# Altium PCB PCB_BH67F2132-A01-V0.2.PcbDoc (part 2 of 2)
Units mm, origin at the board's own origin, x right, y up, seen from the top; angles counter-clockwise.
Board outline 91.52 x 58.18 mm, 2 copper layers (Top Layer, Bottom Layer); 21 components, 47 nets, 172 pads, 84 vias.
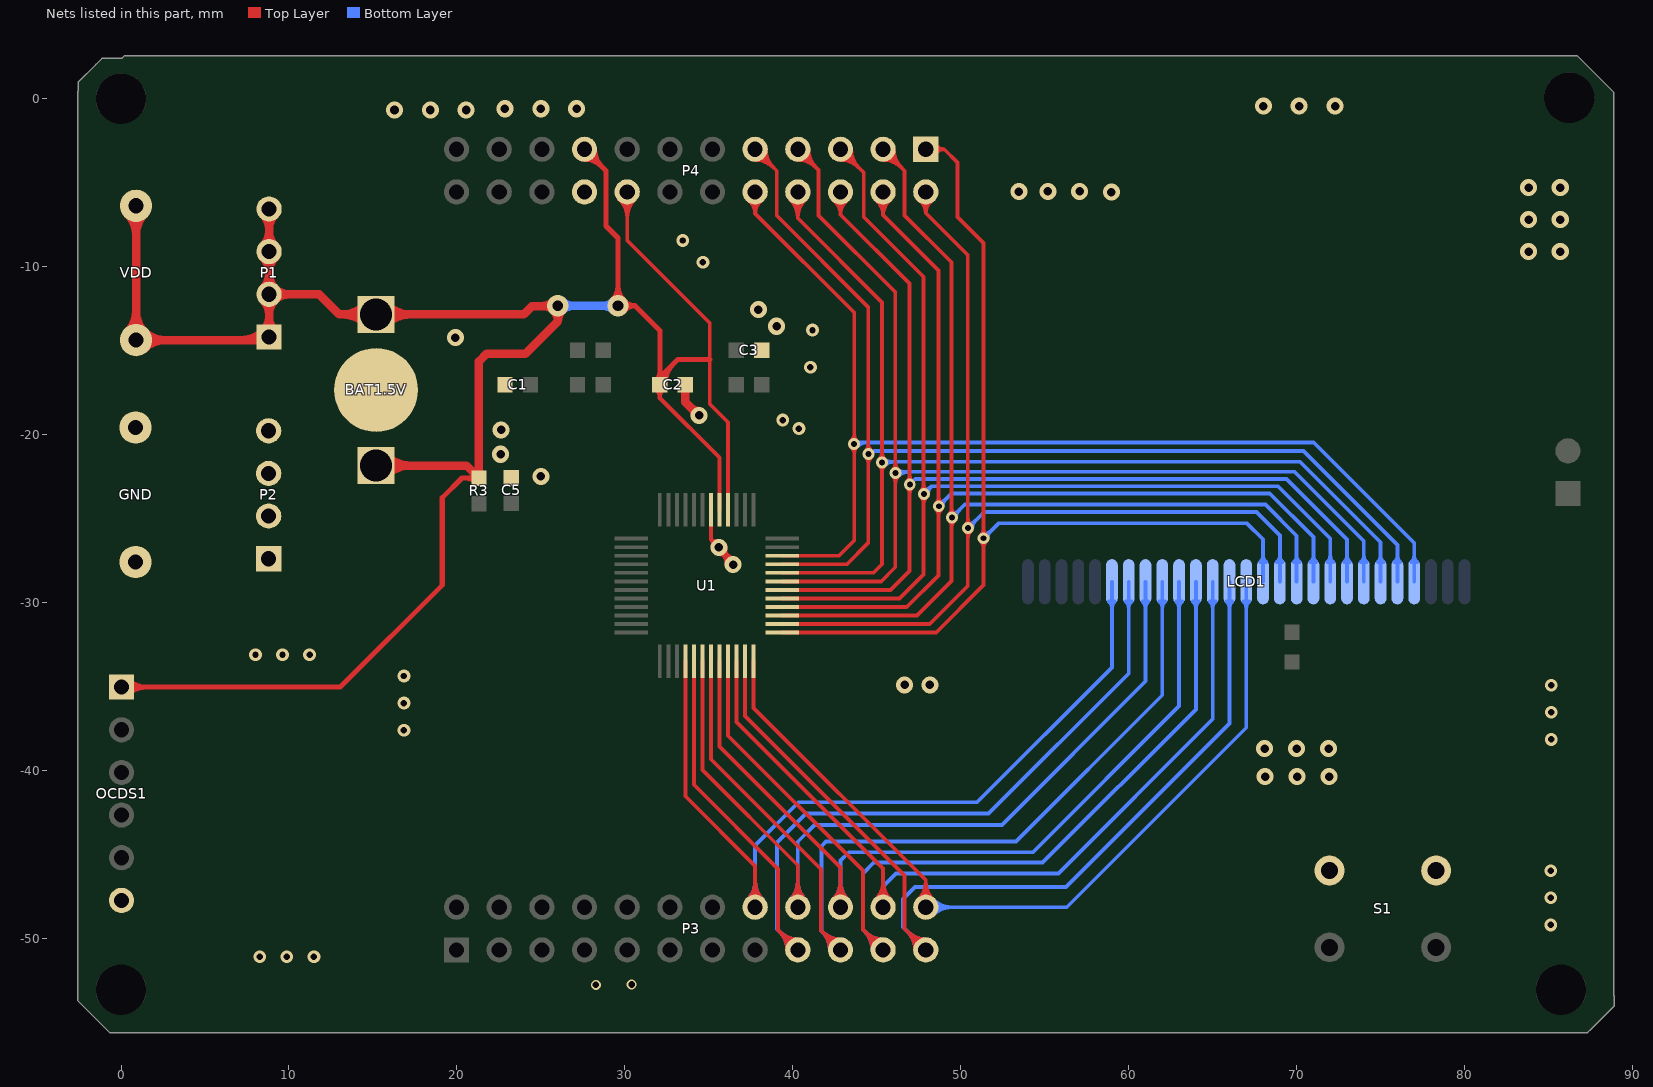
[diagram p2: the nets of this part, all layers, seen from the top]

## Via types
v1: diameter 1.016, hole 0.508, Top Layer to Bottom Layer, tented both sides, 38 vias
v2: diameter 0.762, hole 0.381, Top Layer to Bottom Layer, tented both sides, 23 vias
v3: diameter 0.711, hole 0.356, Top Layer to Bottom Layer, tented both sides, 17 vias
v4: diameter 0.6, hole 0.4, Top Layer to Bottom Layer, tented both sides, 4 vias
v5: diameter 1.27, hole 0.635, Top Layer to Bottom Layer, tented both sides, 2 vias

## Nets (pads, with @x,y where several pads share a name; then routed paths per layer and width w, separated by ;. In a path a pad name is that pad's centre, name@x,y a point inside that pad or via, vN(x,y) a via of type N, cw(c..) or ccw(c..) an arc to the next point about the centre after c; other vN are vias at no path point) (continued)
SEG2: LCD1.4 P4.10 U1.34 | length 72.6
  Top Layer w0.229: P4.10@37.378,-6.056 cw(c36.785,-6.833) 37.763,-6.833 cw(c38.741,-6.833) P4.10@38.148,-6.056 ; P4.10@37.516,-5.874 cw(c37.137,-6.372) 37.763,-6.372 cw(c38.389,-6.372) P4.10@38.01,-5.874 ; P4.10@37.763,-5.55 37.763,-6.833 43.668,-12.738 43.668,-26.302 42.753,-27.216 U1.34@39.385,-27.216 ; v3@43.472,-20.732 cw(c42.999,-21.205) 43.668,-21.205 ; v3@43.472,-20.391 ccw(c42.999,-19.917) 43.668,-19.917 ; 43.668,-21.082 cw(c44.164,-21.082) v3@43.813,-20.732 ; 43.668,-20.04 ccw(c44.164,-20.04) v3@43.813,-20.391
  Bottom Layer w0.229: v3(43.642,-20.561) 43.731,-20.472 71.024,-20.472 77.007,-26.456 LCD1.4@77.007,-28.765 ; v3@43.813,-20.732 cw(c44.44,-21.358) 44.44,-20.472 ; v3@43.813,-20.391 ccw(c44.01,-20.193) 44.01,-20.472 ; LCD1.4@76.841,-27.599 ccw(c76.438,-27.196) 77.007,-27.196 ccw(c77.576,-27.196) LCD1.4@77.174,-27.599
SEG3: LCD1.5 P4.9 U1.33 | length 74.6
  Top Layer w0.229: P4.9@37.763,-3.645 cw(c37.763,-5.18) 38.848,-4.095 cw(c39.933,-3.01) P4.9@38.399,-3.01 ; P4.9@37.763,-3.417 cw(c37.763,-4.4) 38.458,-3.705 cw(c39.153,-3.01) P4.9@38.17,-3.01 ; P4.9@37.763,-3.01 39.045,-4.292 39.045,-6.947 44.493,-12.395 44.493,-26.467 43.236,-27.724 U1.33@39.385,-27.724 ; v3@44.348,-21.316 cw(c43.997,-21.667) 44.493,-21.667 ; v3@44.348,-20.975 ccw(c43.997,-20.624) 44.493,-20.624 ; 44.493,-21.789 cw(c45.163,-21.789) v3@44.689,-21.316 ; 44.493,-20.502 ccw(c45.163,-20.502) v3@44.689,-20.975
  Bottom Layer w0.229: v3(44.519,-21.145) 44.684,-20.98 70.414,-20.98 76.007,-26.574 LCD1.5@76.007,-28.765 ; LCD1.5@75.841,-27.599 ccw(c75.438,-27.196) 76.007,-27.196 ccw(c76.576,-27.196) LCD1.5@76.174,-27.599
SEG4: LCD1.6 P4.8 U1.32 | length 72
  Top Layer w0.229: U1.32@39.385,-28.232 44.811,-28.232 45.319,-27.724 v3(45.319,-21.653) 45.319,-12.128 40.303,-7.113 P4.8@40.303,-5.55 ; P4.8@39.853,-5.999 cw(c38.768,-7.085) 40.303,-7.085 cw(c41.838,-7.085) P4.8@40.753,-5.999 ; P4.8@40.015,-5.838 cw(c39.32,-6.533) 40.303,-6.533 cw(c41.286,-6.533) P4.8@40.591,-5.838 ; v3@45.148,-21.824 cw(c44.736,-22.236) 45.319,-22.236 cw(c45.901,-22.236) v3@45.489,-21.824 ; v3@45.148,-21.483 ccw(c44.736,-21.071) 45.319,-21.071 ccw(c45.901,-21.071) v3@45.489,-21.483
  Bottom Layer w0.229: v3(45.319,-21.653) 45.357,-21.615 70.211,-21.615 75.007,-26.412 LCD1.6@75.007,-28.765 ; v3@45.489,-21.824 cw(c45.993,-22.328) 45.993,-21.615 ; v3@45.489,-21.483 ccw(c45.809,-21.163) 45.809,-21.615 ; LCD1.6@74.841,-27.599 ccw(c74.438,-27.196) 75.007,-27.196 ccw(c75.576,-27.196) LCD1.6@75.174,-27.599
SEG5: LCD1.7 P4.7 U1.31 | length 74
  Top Layer w0.229: U1.31@39.385,-28.74 45.268,-28.74 46.106,-27.902 46.106,-11.519 41.534,-6.947 41.534,-4.241 P4.7@40.303,-3.01 ; P4.7@40.303,-3.645 cw(c40.303,-5.18) 41.388,-4.095 cw(c42.473,-3.01) P4.7@40.939,-3.01 ; P4.7@40.303,-3.417 cw(c40.303,-4.4) 40.998,-3.705 cw(c41.693,-3.01) P4.7@40.71,-3.01 ; v3@45.961,-22.459 cw(c45.61,-22.81) 46.106,-22.81 ; v3@45.961,-22.118 ccw(c45.61,-21.767) 46.106,-21.767 ; 46.106,-22.932 cw(c46.775,-22.932) v3@46.302,-22.459 ; 46.106,-21.645 ccw(c46.775,-21.645) v3@46.302,-22.118
  Bottom Layer w0.229: v3(46.132,-22.288) 46.208,-22.212 69.881,-22.212 74.007,-26.339 LCD1.7@74.007,-28.765 ; v3@46.302,-22.459 cw(c46.898,-23.055) 46.898,-22.212 ; v3@46.302,-22.118 ccw(c46.53,-21.89) 46.53,-22.212 ; LCD1.7@73.841,-27.599 ccw(c73.438,-27.196) 74.007,-27.196 ccw(c74.576,-27.196) LCD1.7@74.174,-27.599
SEG6: LCD1.8 P4.6 U1.30 | length 68.5
  Top Layer w0.229: U1.30@39.385,-29.248 45.827,-29.248 46.944,-28.13 46.944,-11.011 42.843,-6.909 ; P4.6@42.435,-6.038 cw(c41.707,-6.909) 42.843,-6.909 ; P4.6@42.582,-5.862 cw(c42.116,-6.42) 42.843,-6.42 cw(c43.57,-6.42) P4.6@43.104,-5.862 ; P4.6@42.843,-5.55 42.843,-6.909 ; P4.6@43.251,-6.038 ccw(c43.979,-6.909) 42.843,-6.909 ; v3@46.799,-23.145 cw(c46.449,-23.495) 46.944,-23.495 ; v3@46.799,-22.804 ccw(c46.449,-22.453) 46.944,-22.453 ; 46.944,-23.618 cw(c47.614,-23.618) v3@47.14,-23.145 ; 46.944,-22.33 ccw(c47.614,-22.33) v3@47.14,-22.804
  Bottom Layer w0.229: v3(46.97,-22.974) 47.3,-22.644 69.398,-22.644 73.007,-26.253 LCD1.8@73.007,-28.765 ; LCD1.8@72.841,-27.599 ccw(c72.438,-27.196) 73.007,-27.196 ccw(c73.576,-27.196) LCD1.8@73.174,-27.599
SEG7: LCD1.9 P4.5 U1.29 | length 72.2
  Top Layer w0.229: U1.29@39.385,-29.756 46.36,-29.756 47.783,-28.334 47.783,-10.604 44.227,-7.048 44.227,-4.393 P4.5@42.843,-3.01 ; P4.5@42.843,-3.645 cw(c42.843,-5.18) 43.928,-4.095 cw(c45.013,-3.01) P4.5@43.479,-3.01 ; P4.5@42.843,-3.417 cw(c42.843,-4.4) 43.538,-3.705 cw(c44.233,-3.01) P4.5@43.25,-3.01 ; v3@47.637,-23.704 cw(c47.287,-24.054) 47.783,-24.054 ; v3@47.637,-23.362 ccw(c47.287,-23.012) 47.783,-23.012 ; 47.783,-24.177 cw(c48.452,-24.177) v3@47.979,-23.704 ; 47.783,-22.889 ccw(c48.452,-22.889) v3@47.979,-23.362
  Bottom Layer w0.229: v3(47.808,-23.533) 48.265,-23.076 68.89,-23.076 72.007,-26.193 LCD1.9@72.007,-28.765 ; v3@47.808,-23.292 ccw(c47.808,-22.709) 48.22,-23.121 ccw(c48.632,-23.533) v3@48.049,-23.533 ; LCD1.9@71.841,-27.599 ccw(c71.438,-27.196) 72.007,-27.196 ccw(c72.576,-27.196) LCD1.9@72.174,-27.599
SEG8: LCD1.10 P4.4 U1.28 | length 67.6
  Top Layer w0.229: U1.28@39.385,-30.264 46.792,-30.264 48.672,-28.384 48.672,-10.223 45.383,-6.935 ; P4.4@44.969,-6.032 cw(c44.192,-6.935) 45.383,-6.935 ; P4.4@45.118,-5.858 cw(c44.62,-6.437) 45.383,-6.437 cw(c46.146,-6.437) P4.4@45.648,-5.858 ; P4.4@45.383,-5.55 45.383,-6.935 ; P4.4@45.797,-6.032 ccw(c46.574,-6.935) 45.383,-6.935 ; v3@48.526,-24.44 cw(c48.176,-24.791) 48.672,-24.791 ; v3@48.526,-24.099 ccw(c48.176,-23.748) 48.672,-23.748 ; 48.672,-24.913 cw(c49.341,-24.913) v3@48.868,-24.44 ; 48.672,-23.626 ccw(c49.341,-23.626) v3@48.868,-24.099
  Bottom Layer w0.229: v3(48.697,-24.27) 49.459,-23.508 68.407,-23.508 71.007,-26.108 LCD1.10@71.007,-28.765 ; v3@48.697,-24.028 ccw(c48.697,-23.446) 49.109,-23.858 ccw(c49.521,-24.27) v3@48.938,-24.27 ; LCD1.10@70.841,-27.599 ccw(c70.438,-27.196) 71.007,-27.196 ccw(c71.576,-27.196) LCD1.10@71.174,-27.599
SEG9: LCD1.11 P4.3 U1.27 | length 70.3
  Top Layer w0.229: U1.27@39.385,-30.772 47.402,-30.772 49.459,-28.715 49.459,-9.741 46.665,-6.947 46.665,-4.292 P4.3@45.383,-3.01 ; P4.3@45.383,-3.645 cw(c45.383,-5.18) 46.468,-4.095 cw(c47.553,-3.01) P4.3@46.019,-3.01 ; P4.3@45.383,-3.417 cw(c45.383,-4.4) 46.078,-3.705 cw(c46.773,-3.01) P4.3@45.79,-3.01 ; v3@49.314,-25.101 cw(c48.963,-25.451) 49.459,-25.451 ; v3@49.314,-24.759 ccw(c48.963,-24.409) 49.459,-24.409 ; 49.459,-25.574 cw(c50.128,-25.574) v3@49.655,-25.101 ; 49.459,-24.286 ccw(c50.128,-24.286) v3@49.655,-24.759
  Bottom Layer w0.229: v3(49.484,-24.93) 50.246,-24.168 68.153,-24.168 70.007,-26.022 LCD1.11@70.007,-28.765 ; v3@49.484,-24.689 ccw(c49.484,-24.106) 49.896,-24.518 ccw(c50.308,-24.93) v3@49.726,-24.93 ; LCD1.11@69.841,-27.599 ccw(c69.438,-27.196) 70.007,-27.196 ccw(c70.576,-27.196) LCD1.11@70.174,-27.599
SEG10: LCD1.12 P4.2 U1.26 | length 65.3
  Top Layer w0.229: U1.26@39.385,-31.28 48.164,-31.28 50.424,-29.019 50.424,-9.309 47.923,-6.808 ; P4.2@47.546,-6.062 cw(c46.996,-6.808) 47.923,-6.808 ; P4.2@47.682,-5.878 cw(c47.329,-6.355) 47.923,-6.355 cw(c48.517,-6.355) P4.2@48.164,-5.878 ; P4.2@47.923,-5.55 47.923,-6.808 ; P4.2@48.3,-6.062 ccw(c48.85,-6.808) 47.923,-6.808 ; v3@50.279,-25.736 cw(c49.928,-26.086) 50.424,-26.086 ; v3@50.279,-25.394 ccw(c49.928,-25.044) 50.424,-25.044 ; 50.424,-26.209 cw(c51.093,-26.209) v3@50.62,-25.736 ; 50.424,-24.921 ccw(c51.093,-24.921) v3@50.62,-25.394
  Bottom Layer w0.229: v3(50.45,-25.565) 51.402,-24.613 67.607,-24.613 69.007,-26.013 LCD1.12@69.007,-28.765 ; v3@50.45,-25.324 ccw(c50.45,-24.741) 50.862,-25.153 ccw(c51.273,-25.565) v3@50.691,-25.565 ; LCD1.12@68.841,-27.599 ccw(c68.438,-27.196) 69.007,-27.196 ccw(c69.576,-27.196) LCD1.12@69.174,-27.599
SEG11: LCD1.13 P4.1 U1.25 | length 66.1
  Top Layer w0.229: U1.25@39.385,-31.788 48.545,-31.788 51.364,-28.969 v3(51.364,-26.175) 51.364,-8.598 49.815,-7.048 49.815,-3.801 49.023,-3.01 ; P4.1@47.923,-3.01 49.023,-3.01 ; P4.1@48.474,-3.327 cw(c49.023,-3.644) 49.023,-3.01 ; P4.1@48.474,-2.692 ccw(c49.023,-2.376) 49.023,-3.01 ; v3@51.193,-26.345 cw(c50.781,-26.757) 51.364,-26.757 cw(c51.947,-26.757) v3@51.535,-26.345 ; v3@51.193,-26.004 ccw(c50.781,-25.592) 51.364,-25.592 ccw(c51.947,-25.592) v3@51.535,-26.004
  Bottom Layer w0.229: v3(51.364,-26.175) 52.253,-25.286 67.061,-25.286 68.007,-26.232 LCD1.13@68.007,-28.765 ; v3@51.364,-25.933 ccw(c51.364,-25.351) 51.776,-25.763 ccw(c52.188,-26.175) v3@51.605,-26.175 ; LCD1.13@67.841,-27.599 ccw(c67.438,-27.196) 68.007,-27.196 ccw(c68.576,-27.196) LCD1.13@68.174,-27.599
SEG12: LCD1.14 P3.24 U1.24 | length 59.9
  Top Layer w0.229: U1.24@37.673,-33.499 37.673,-36.284 47.923,-46.534 P3.24@47.923,-48.146 ; P3.24@47.474,-47.696 ccw(c46.388,-46.611) 47.923,-46.611 ccw(c49.458,-46.611) P3.24@48.373,-47.696 ; P3.24@47.635,-47.858 ccw(c46.94,-47.163) 47.923,-47.163 ccw(c48.906,-47.163) P3.24@48.211,-47.858
  Bottom Layer w0.229: P3.24@47.923,-48.146 56.317,-48.146 67.007,-37.455 LCD1.14@67.007,-28.765 ; P3.24@48.211,-48.433 cw(c48.906,-49.128) 48.906,-48.146 cw(c48.906,-47.163) P3.24@48.211,-47.858 ; P3.24@48.373,-48.595 cw(c49.458,-49.68) 49.458,-48.146 cw(c49.458,-46.611) P3.24@48.373,-47.696 ; LCD1.14@66.841,-29.932 cw(c66.438,-30.334) 67.007,-30.334 cw(c67.576,-30.334) LCD1.14@67.174,-29.932
SEG13: LCD1.15 P3.23 U1.23 | length 66.2
  Top Layer w0.229: U1.23@37.165,-33.499 37.165,-36.766 46.665,-46.266 46.665,-49.427 P3.23@47.923,-50.686 ; P3.23@47.287,-50.686 ccw(c45.753,-50.686) 46.838,-49.6 ccw(c47.923,-48.515) P3.23@47.923,-50.05 ; P3.23@47.516,-50.686 ccw(c46.533,-50.686) 47.228,-49.991 ccw(c47.923,-49.296) P3.23@47.923,-50.279
  Bottom Layer w0.229: P3.23@47.287,-50.686 ccw(c45.753,-50.686) 46.838,-49.6 ccw(c47.923,-48.515) P3.23@47.923,-50.05 ; P3.23@47.516,-50.686 ccw(c46.533,-50.686) 47.228,-49.991 ccw(c47.923,-49.296) P3.23@47.923,-50.279 ; P3.23@47.923,-50.686 46.563,-49.326 46.563,-47.663 47.275,-46.952 56.266,-46.952 66.007,-37.211 LCD1.15@66.007,-28.765 ; LCD1.15@65.841,-29.932 cw(c65.438,-30.334) 66.007,-30.334 cw(c66.576,-30.334) LCD1.15@66.174,-29.932
SEG14: LCD1.16 P3.22 U1.22 | length 59
  Top Layer w0.229: U1.22@36.657,-33.499 36.657,-37.122 45.383,-45.848 P3.22@45.383,-48.146 ; P3.22@44.934,-47.696 ccw(c43.848,-46.611) 45.383,-46.611 ccw(c46.918,-46.611) P3.22@45.833,-47.696 ; P3.22@45.095,-47.858 ccw(c44.4,-47.163) 45.383,-47.163 ccw(c46.366,-47.163) P3.22@45.671,-47.858
  Bottom Layer w0.229: P3.22@45.015,-47.628 ccw(c44.506,-46.913) 45.383,-46.913 ; P3.22@45.147,-47.814 ccw(c44.821,-47.356) 45.383,-47.356 ccw(c45.945,-47.356) P3.22@45.619,-47.814 ; P3.22@45.383,-48.146 45.383,-46.913 ; P3.22@45.752,-47.628 cw(c46.26,-46.913) 45.383,-46.913 ; LCD1.16@64.841,-29.932 cw(c64.438,-30.334) 65.007,-30.334 cw(c65.576,-30.334) LCD1.16@65.174,-29.932 ; LCD1.16@65.007,-28.765 65.007,-36.954 55.822,-46.139 46.157,-46.139 45.383,-46.913
SEG15: LCD1.17 P3.21 U1.21 | length 66.3
  Top Layer w0.229: U1.21@36.149,-33.499 36.149,-37.935 44.176,-45.961 44.176,-49.478 P3.21@45.383,-50.686 ; P3.21@44.747,-50.686 ccw(c43.213,-50.686) 44.298,-49.6 ccw(c45.383,-48.515) P3.21@45.383,-50.05 ; P3.21@44.976,-50.686 ccw(c43.993,-50.686) 44.688,-49.991 ccw(c45.383,-49.296) P3.21@45.383,-50.279
  Bottom Layer w0.229: P3.21@44.747,-50.686 ccw(c43.213,-50.686) 44.298,-49.6 ccw(c45.383,-48.515) P3.21@45.383,-50.05 ; P3.21@44.976,-50.686 ccw(c43.993,-50.686) 44.688,-49.991 ccw(c45.383,-49.296) P3.21@45.383,-50.279 ; P3.21@45.383,-50.686 44.176,-49.478 44.176,-46.139 44.824,-45.491 54.882,-45.491 64.007,-36.366 LCD1.17@64.007,-28.765 ; LCD1.17@63.841,-29.932 cw(c63.438,-30.334) 64.007,-30.334 cw(c64.576,-30.334) LCD1.17@64.174,-29.932
SEG16: LCD1.18 P3.20 U1.20 | length 60.6
  Top Layer w0.229: U1.20@35.641,-33.499 35.641,-38.57 42.843,-45.772 P3.20@42.843,-48.146 ; P3.20@42.394,-47.696 ccw(c41.308,-46.611) 42.843,-46.611 ccw(c44.378,-46.611) P3.20@43.293,-47.696 ; P3.20@42.555,-47.858 ccw(c41.86,-47.163) 42.843,-47.163 ccw(c43.826,-47.163) P3.20@43.131,-47.858
  Bottom Layer w0.229: P3.20@42.394,-47.696 ccw(c41.308,-46.611) 42.843,-46.611 ccw(c44.378,-46.611) P3.20@43.293,-47.696 ; P3.20@42.555,-47.858 ccw(c41.86,-47.163) 42.843,-47.163 ccw(c43.826,-47.163) P3.20@43.131,-47.858 ; P3.20@42.843,-48.146 42.843,-45.363 43.338,-44.869 54.31,-44.869 63.007,-36.172 LCD1.18@63.007,-28.765 ; LCD1.18@62.841,-29.932 cw(c62.438,-30.334) 63.007,-30.334 cw(c63.576,-30.334) LCD1.18@63.174,-29.932
SEG17: LCD1.19 P3.19 U1.19 | length 66.6
  Top Layer w0.229: U1.19@35.133,-33.499 35.133,-39.332 41.687,-45.885 41.687,-49.529 P3.19@42.843,-50.686 ; P3.19@42.207,-50.686 ccw(c40.673,-50.686) 41.758,-49.6 ccw(c42.843,-48.515) P3.19@42.843,-50.05 ; P3.19@42.436,-50.686 ccw(c41.453,-50.686) 42.148,-49.991 ccw(c42.843,-49.296) P3.19@42.843,-50.279
  Bottom Layer w0.229: P3.19@42.207,-50.686 ccw(c40.673,-50.686) 41.758,-49.6 ccw(c42.843,-48.515) P3.19@42.843,-50.05 ; P3.19@42.436,-50.686 ccw(c41.453,-50.686) 42.148,-49.991 ccw(c42.843,-49.296) P3.19@42.843,-50.279 ; P3.19@42.843,-50.686 41.712,-49.554 41.712,-44.513 41.991,-44.234 53.294,-44.234 62.007,-35.521 LCD1.19@62.007,-28.765 ; LCD1.19@61.841,-29.932 cw(c61.438,-30.334) 62.007,-30.334 cw(c62.576,-30.334) LCD1.19@62.174,-29.932
SEG18: LCD1.20 P3.18 U1.18 | length 60.3
  Top Layer w0.229: U1.18@34.625,-33.499 34.625,-39.967 40.303,-45.645 P3.18@40.303,-48.146 ; P3.18@39.854,-47.696 ccw(c38.768,-46.611) 40.303,-46.611 ccw(c41.838,-46.611) P3.18@40.753,-47.696 ; P3.18@40.015,-47.858 ccw(c39.32,-47.163) 40.303,-47.163 ccw(c41.286,-47.163) P3.18@40.591,-47.858
  Bottom Layer w0.229: P3.18@39.854,-47.696 ccw(c38.768,-46.611) 40.303,-46.611 ccw(c41.838,-46.611) P3.18@40.753,-47.696 ; P3.18@40.015,-47.858 ccw(c39.32,-47.163) 40.303,-47.163 ccw(c41.286,-47.163) P3.18@40.591,-47.858 ; P3.18@40.303,-48.146 40.303,-44.246 41.306,-43.243 52.456,-43.243 61.007,-34.692 LCD1.20@61.007,-28.765 ; LCD1.20@60.841,-29.932 cw(c60.438,-30.334) 61.007,-30.334 cw(c61.576,-30.334) LCD1.20@61.174,-29.932
SEG19: LCD1.21 P3.17 U1.17 | length 66
  Top Layer w0.229: U1.17@34.117,-33.499 34.117,-40.856 39.121,-45.86 39.121,-49.504 P3.17@40.303,-50.686 ; P3.17@39.667,-50.686 ccw(c38.133,-50.686) 39.218,-49.6 ccw(c40.303,-48.515) P3.17@40.303,-50.05 ; P3.17@39.896,-50.686 ccw(c38.913,-50.686) 39.608,-49.991 ccw(c40.303,-49.296) P3.17@40.303,-50.279
  Bottom Layer w0.229: P3.17@39.667,-50.686 ccw(c38.133,-50.686) 39.218,-49.6 ccw(c40.303,-48.515) P3.17@40.303,-50.05 ; P3.17@39.896,-50.686 ccw(c38.913,-50.686) 39.608,-49.991 ccw(c40.303,-49.296) P3.17@40.303,-50.279 ; P3.17@40.303,-50.686 39.07,-49.453 39.07,-44.285 40.798,-42.558 51.669,-42.558 60.007,-34.219 LCD1.21@60.007,-28.765 ; LCD1.21@59.841,-29.932 cw(c59.438,-30.334) 60.007,-30.334 cw(c60.576,-30.334) LCD1.21@60.174,-29.932
SEG20: LCD1.22 P3.16 U1.16 | length 59.6
  Top Layer w0.229: U1.16@33.609,-33.499 33.609,-41.542 37.763,-45.695 P3.16@37.763,-48.146 ; P3.16@37.314,-47.696 ccw(c36.228,-46.611) 37.763,-46.611 ccw(c39.298,-46.611) P3.16@38.213,-47.696 ; P3.16@37.475,-47.858 ccw(c36.78,-47.163) 37.763,-47.163 ccw(c38.746,-47.163) P3.16@38.051,-47.858
  Bottom Layer w0.229: P3.16@37.314,-47.696 ccw(c36.228,-46.611) 37.763,-46.611 ccw(c39.298,-46.611) P3.16@38.213,-47.696 ; P3.16@37.475,-47.858 ccw(c36.78,-47.163) 37.763,-47.163 ccw(c38.746,-47.163) P3.16@38.051,-47.858 ; P3.16@37.763,-48.146 37.763,-44.474 40.34,-41.897 50.983,-41.897 59.007,-33.873 LCD1.22@59.007,-28.765 ; LCD1.22@58.841,-29.932 cw(c58.438,-30.334) 59.007,-30.334 cw(c59.576,-30.334) LCD1.22@59.174,-29.932
VDD: BAT1.5V.1 C2.1 OCDS1.1 P1.1 P1.2 P1.3 P1.4 P4.16 P4.17 R3.1 U1.40 U1.41 VDD.1 VDD.2 | length 202.4
  Top Layer w0.229: P4.16@29.693,-5.999 cw(c28.608,-7.085) 30.143,-7.085 cw(c31.678,-7.085) P4.16@30.593,-5.999 ; P4.16@29.855,-5.838 cw(c29.16,-6.533) 30.143,-6.533 cw(c31.126,-6.533) P4.16@30.431,-5.838 ; P4.16@30.143,-5.55 30.143,-8.451 35.057,-13.366 35.057,-15.519 35.057,-18.174 36.149,-19.266 U1.40@36.149,-24.489
  Top Layer w0.254: C2.1@31.854,-17.266 cw(c31.312,-17.818) 32.085,-17.818 ; C2.1@32.085,-17.031 32.085,-17.818 ; C2.1@32.317,-17.266 ccw(c32.859,-17.818) 32.085,-17.818 ; U1.41@35.641,-24.489 35.641,-21.374 32.085,-17.818
  Top Layer w0.305: OCDS1.1@0.031,-35.039 13.061,-35.039 19.131,-28.969 19.131,-23.762 20.3,-22.593 R3.1@21.316,-22.593 ; OCDS1.1@0.453,-35.462 cw(c1.473,-36.482) 1.473,-35.039 cw(c1.473,-33.596) OCDS1.1@0.453,-34.617 ; R3.1@21.1,-22.809 ccw(c20.58,-23.329) 20.58,-22.593 ccw(c20.58,-21.857) R3.1@21.1,-22.378 ; P4.17@27.603,-3.607 cw(c27.603,-5.05) 28.623,-4.03 cw(c29.643,-3.01) P4.17@28.201,-3.01 ; P4.17@27.603,-3.01 28.885,-4.292 28.885,-7.582 29.596,-8.293 v5(29.596,-12.332) 30.612,-12.332 ; v5@29.255,-11.99 ccw(c28.431,-11.167) 29.596,-11.167 ccw(c30.761,-11.167) v5@29.937,-11.99 ; v5@29.97,-12.637 cw(c30.612,-13.16) 30.612,-12.332 ; v5@29.97,-12.027 ccw(c30.612,-11.504) 30.612,-12.332 ; C2.1@31.87,-16.815 ccw(c31.35,-16.295) 32.085,-16.295 ccw(c32.821,-16.295) C2.1@32.301,-16.815 ; 32.385,-16.306 ccw(c33.11,-17.031) C2.1@32.085,-17.031 C2.1@32.085,-16.606 ; C2.1@32.39,-17.031 cw(c34.15,-17.031) 32.906,-15.786 ; 35.057,-15.519 33.172,-15.519 C2.1@32.085,-16.606 ; 30.612,-12.332 32.085,-13.805 C2.1@32.085,-16.606
  Top Layer w0.508: VDD.1@0.394,-13.875 ccw(c-0.815,-12.667) 0.894,-12.667 ccw(c2.603,-12.667) 1.395,-13.875 ccw(c2.603,-12.667) 2.603,-14.376 ccw(c2.603,-16.085) VDD.1@1.395,-14.876 ; VDD.2@0.394,-6.876 cw(c-0.815,-8.085) 0.894,-8.085 cw(c2.603,-8.085) VDD.2@1.395,-6.876 ; VDD.2@0.894,-6.376 VDD.1@0.894,-14.376 8.629,-14.376 P1.1@8.819,-14.186 P1.2@8.819,-11.646 ; 7.163,-14.376 ccw(c7.163,-12.53) 8.468,-13.835 ccw(c7.622,-12.988) 8.819,-12.988 ccw(c10.016,-12.988) P1.1@9.17,-13.835 ; P1.1@8.08,-14.376 cw(c8.08,-14.925) P1.1@8.468,-14.537 ; P1.2@8.468,-11.997 cw(c7.622,-12.843) 8.819,-12.843 cw(c10.016,-12.843) 9.17,-11.997 cw(c10.016,-12.843) 10.016,-11.646 cw(c10.016,-10.448) 9.17,-11.295 cw(c10.016,-10.448) 8.819,-10.448 cw(c7.622,-10.448) P1.2@8.468,-11.295 ; P1.3@8.468,-9.457 cw(c7.622,-10.303) 8.819,-10.303 cw(c10.016,-10.303) P1.3@9.17,-9.457 ; P1.3@8.468,-8.755 ccw(c7.622,-7.908) 8.819,-7.908 ccw(c10.016,-7.908) P1.3@9.17,-8.755 ; P1.4@8.468,-6.917 cw(c7.622,-7.763) 8.819,-7.763 cw(c10.016,-7.763) P1.4@9.17,-6.917 ; P1.4@8.819,-6.566 P1.3@8.819,-9.106 P1.2@8.819,-11.646 ; BAT1.5V.1@14.591,-13.442 ccw(c13.147,-14.886) 13.147,-12.844 ccw(c13.147,-10.802) BAT1.5V.1@14.591,-12.246 ; BAT1.5V.1@15.189,-21.844 20.567,-21.844 R3.1@21.316,-22.593 21.316,-15.641 21.768,-15.189 24.079,-15.189 26.015,-13.254 26.015,-12.357 24.473,-12.357 23.986,-12.844 BAT1.5V.1@15.189,-12.844 12.996,-12.844 11.798,-11.646 P1.2@8.819,-11.646 ; BAT1.5V.1@15.787,-22.442 cw(c17.232,-23.886) 17.232,-21.844 cw(c17.232,-19.802) BAT1.5V.1@15.787,-21.246 ; BAT1.5V.1@15.787,-13.442 cw(c17.232,-14.886) 17.232,-12.844 cw(c17.232,-10.802) BAT1.5V.1@15.787,-12.246 ; R3.1@21.113,-22.593 ccw(c20.622,-22.593) 20.969,-22.246 ccw(c21.316,-21.899) R3.1@21.316,-22.39 ; R3.1@21.172,-22.45 ccw(c20.825,-22.103) 21.316,-22.103 ccw(c21.806,-22.103) R3.1@21.459,-22.45 ; 25.034,-12.357 ccw(c25.034,-11.35) v5@25.745,-12.062 ; 25.156,-12.357 cw(c25.156,-13.19) 25.745,-12.601 cw(c25.095,-13.251) 26.015,-13.251 cw(c26.935,-13.251) v5@26.284,-12.601
  Bottom Layer w0.508: v5(26.015,-12.332) v5(29.596,-12.332) ; v5@26.284,-12.601 cw(c26.935,-13.251) 26.935,-12.332 cw(c26.935,-11.412) v5@26.284,-12.062 ; v5@29.327,-12.601 ccw(c28.676,-13.251) 28.676,-12.332 ccw(c28.676,-11.412) v5@29.327,-12.062
VSS: BAT1.5V.2 C1.1 C2.2 C3.1 C5.2 GND.1 GND.2 OCDS1.6 P2.1 P2.2 P2.3 P2.4 P4.18 S1.2 U1.42 | length 13.3
  Top Layer w0.229: U1.42@35.133,-24.489 35.133,-26.251 ; v1@35.225,-26.61 ccw(c34.876,-26.508) 35.133,-26.251 ; v1@35.493,-26.343 cw(c35.391,-25.993) 35.133,-26.251 ; v1@35.603,-27.114 cw(c35.603,-27.636) 35.972,-27.267 ; v1@35.768,-26.721 ccw(c36.596,-26.721) 36.011,-27.306 ; v1@35.997,-26.721 ccw(c37.377,-26.721) v1@36.401,-27.696 ; v1@36.06,-27.749 ccw(c35.11,-27.749) 35.782,-27.077 ccw(c36.454,-26.405) v1@36.454,-27.356 ; v1@36.085,-27.613 ccw(c35.481,-27.39) 36.038,-27.068 ccw(c36.544,-26.776) v1@36.49,-27.357 ; v1(36.454,-27.749) 35.603,-26.899 v1(35.603,-26.721) 35.133,-26.251
  Top Layer w0.508: C2.2@33.466,-17.174 cw(c33.119,-17.521) 33.609,-17.521 cw(c34.1,-17.521) C2.2@33.753,-17.174 ; C2.2@33.609,-17.031 33.609,-18.072 v1@34.409,-18.872 ; 33.945,-18.408 ccw(c34.422,-17.931) v1@34.422,-18.605 ; 34.007,-18.469 cw(c33.616,-18.859) v1@34.168,-18.859
  other v1: 68.128,-40.373 70.033,-40.373 71.938,-40.373 68.103,-38.697 70.008,-38.697 71.913,-38.697 46.665,-34.912 48.164,-34.912 24.999,-22.492 22.611,-21.171 22.637,-19.723 34.422,-18.859 19.914,-14.224 39.045,-13.551 37.953,-12.56 83.825,-9.106 85.705,-9.106 83.825,-7.201 85.705,-7.201 58.979,-5.563 53.467,-5.537 55.199,-5.524 57.079,-5.524 83.825,-5.296 85.705,-5.296 16.287,-0.673 18.42,-0.673 20.554,-0.673 22.865,-0.597 24.999,-0.597 27.132,-0.597 68.026,-0.444 70.16,-0.444 72.294,-0.444
  other v2: 8.26,-51.092 9.873,-51.092 11.486,-51.092 85.141,-49.2 85.141,-47.587 85.141,-45.974 85.166,-38.151 16.845,-37.605 85.166,-36.538 16.845,-35.992 85.166,-34.925 16.845,-34.379 8.006,-33.109 9.619,-33.109 11.232,-33.109 40.366,-19.647 39.401,-19.139 41.052,-15.989 41.179,-13.779 34.651,-9.741 33.457,-8.445
  other v4: 28.275,-52.768 30.409,-52.743
pads on no net: LCD1.23 LCD1.24 LCD1.25 OCDS1.2 OCDS1.4

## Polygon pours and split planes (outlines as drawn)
VSS on Top Layer "Top Layer-No Net" (solid, remove dead copper, pour order 10): 0.365,-0.073 85.598,-0.073 85.598,-52.563 85.435,-52.716 85.365,-52.781 0.178,-52.781 0.178,-0.248 0.715,0.254
VSS on Bottom Layer "Top Layer-No Net" (solid, remove dead copper, pour order 12): 0.46,-0.051 0.554,0.036 85.769,0.036 85.769,-52.785 86.284,-53.264 85.84,-52.85 0.273,-52.85 0.273,0.036 0.203,0.102

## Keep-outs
Keep-Out Layer:
  lines w0.203: 52.578,-17.907 52.578,-15.672 81.788,-15.672 81.788,-17.907 52.578,-17.907
  lines w0.508: -2.586,-0.219 -2.586,-52.467 ccw(c0.133,-52.778) 0.256,-55.512 ; -2.578,-0.219 cw(c0.209,-0.219) 0.209,2.568 85.603,2.568 ; 0.256,-55.534 86.52,-55.534 ; 85.349,2.578 cw(c85.222,-1.105) 88.905,-1.232 ; 86.438,-55.534 ccw(c86.52,-53.149) 88.904,-53.231 ; 88.905,-53.149 88.905,-0.978

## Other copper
Top Layer:
  pour cut-out: 52.527,-10.668 82.423,-10.668 82.448,-10.643 82.448,-18.39 52.578,-18.39 52.527,-18.339
  pour cut-out: 51.062,-7.582 52.609,-7.582 52.558,-7.633 52.558,-26.702 51.199,-26.702 51.181,-26.721 51.062,-26.602
Bottom Layer:
  pour cut-out: 41.885,-17.78 52.375,-17.78 52.426,-17.729 52.451,-17.755 52.451,-18.694 41.885,-18.694 41.859,-18.669 41.885,-18.644
  pour cut-out: 81.006,-26.225 81.006,-26.251 52.1,-26.224 52.05,-30.848 66.274,-30.848 80.549,-30.874 81.133,-30.874 80.98,-28.486 80.98,-27.419
  pour cut-out: 52.146,-15.113 52.146,-16.815 52.146,-18.618 82.474,-18.644 82.499,-18.669 82.55,-18.618 82.55,-14.91 52.629,-14.91 52.146,-14.961

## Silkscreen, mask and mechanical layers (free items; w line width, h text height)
Top Overlay:
  drawing of 9406 lines, arcs and shapes, not listed
  text "SEG1" at 33.99,-0.267 h1.02
  text "Power_In" at 2.901,-1.41 h2.54
  text "1.1V~2.2V" at 2.819,-4.648 h2.39
  text "SEG0" at 33.787,-9.411 h1.02
  text "RREF" at 26.37,-10.985 h1.27
  text "NTC" at 26.447,-12.916 h1.27
  text "LCD" at 52.736,-15.227 h2.54
  text "CREF" at 20.98,-15.316 h1.27
  text "Sensor" at 76.454,-24.994 h2.54
  text "VDD" at 2.418,-35.547 h1.78
  text "BH67F2132" at 26.797,-39.827 h3.05
  text "ICPCK" at 1.758,-40.78 h1.78
  text "BEEP" at 81.869,-40.983 h2.54
  text "COM1" at 33.635,-45.275 h1.02
  text "ICPDA" at 1.58,-45.529 h1.78
  text "GND" at 2.317,-48.273 h1.78
  text "BH67F2132_V0.2" at 52.603,-49.682 h1.78
  text "2020/04/25" at 57.125,-51.867 h1.78
  text "COM0" at 33.635,-54.572 h1.02
  text "KEY" at 52.685,-54.648 h2.54
  text "E_Link" at 7.061,-54.712 h2.54
  text "PCB 工藝: 板厚1MM" at 24.13,-65.964 h4
Bottom Overlay:
  circle w1: c25.384,-13.602 r5
  circle w1: c77.457,-6.099 r5
  circle w1: c63.865,-43.396 r5
  circle w1: c16.801,-40.237 r5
